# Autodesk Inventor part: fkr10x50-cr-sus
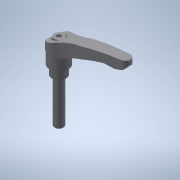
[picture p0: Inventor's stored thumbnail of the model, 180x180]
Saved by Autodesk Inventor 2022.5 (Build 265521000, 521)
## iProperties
Created: 2017-09
Part Number: fkr10x50-cr-sus
Material: 一般
Document SubType Name: Modeling
Designer: imaocorp
Density: 1 g/cm^3
Appearance: 既定
Author: imaocorp
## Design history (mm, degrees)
node "fkr10x50-cr-sus.x_t1"
node "fkr10x50-cr-sus"
node "Base1"
